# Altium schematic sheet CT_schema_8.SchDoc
size 277 x 170 mm
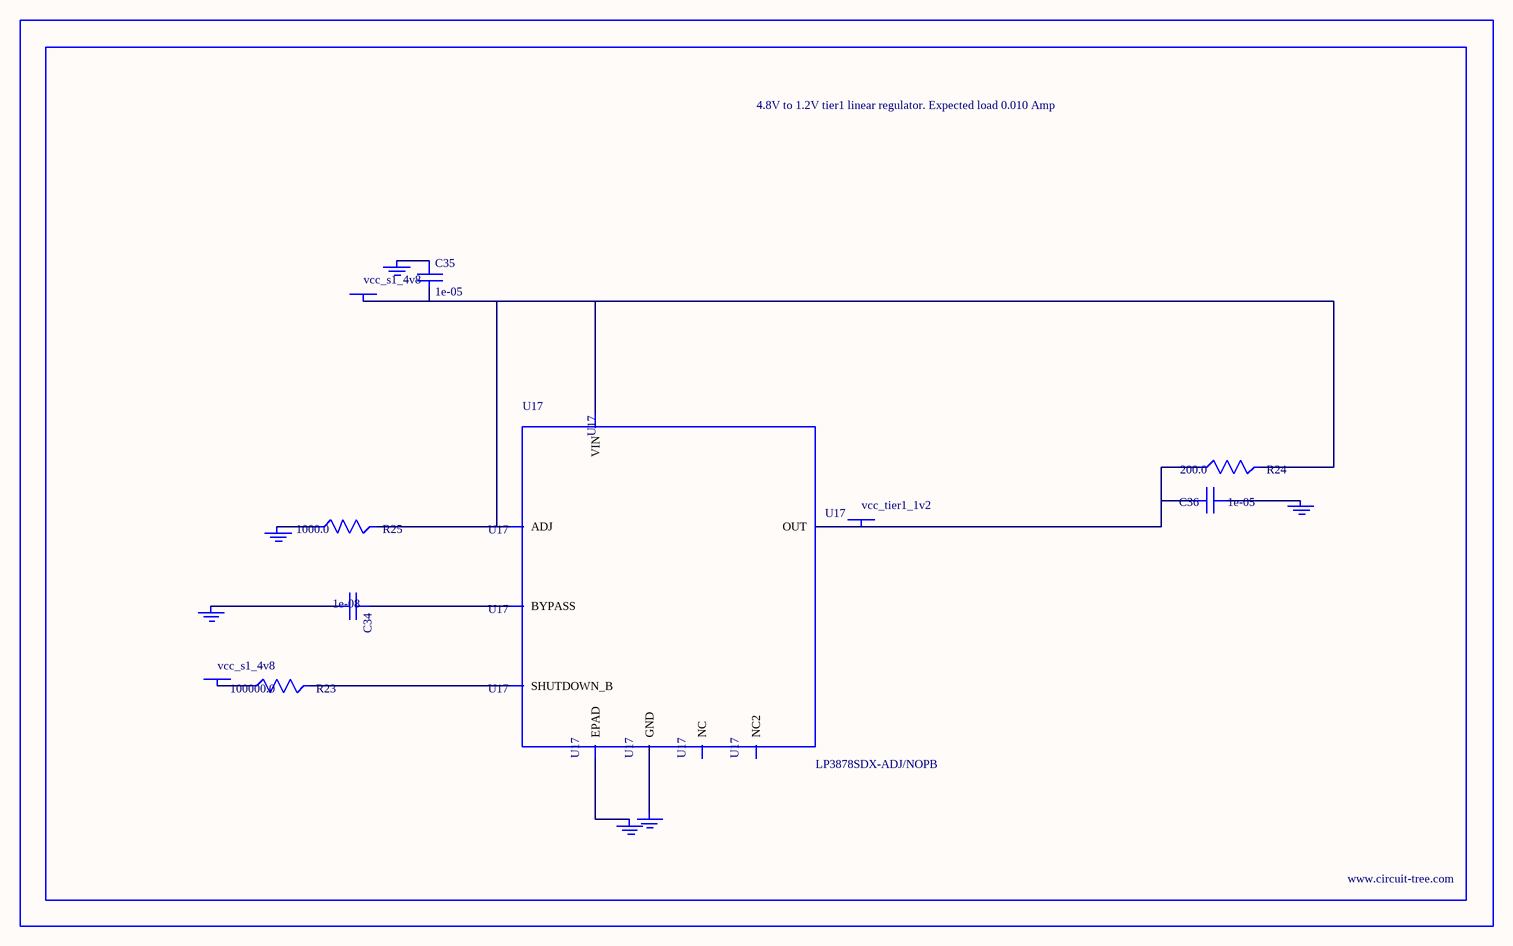
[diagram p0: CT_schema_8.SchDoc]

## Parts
BORDER7  (no value)
C34  1e-08  [C0402]
C35  1e-05  [C1206]
C36  1e-05  [C0805]
GND_INSTANCE_7_0  (no value)
GND_INSTANCE_7_1  (no value)
GND_INSTANCE_7_2  (no value)
GND_INSTANCE_7_3  (no value)
GND_INSTANCE_7_4  (no value)
GND_INSTANCE_7_5  (no value)
POWER_INSTANCE_7_0  vcc_s1_4v8
POWER_INSTANCE_7_1  vcc_s1_4v8
POWER_INSTANCE_7_2  vcc_tier1_1v2
R23  100000.0  [R0603]
R24  200.0  [R0603]
R25  1000.0  [R0603]
U17  LP3878SDX-ADJ/NOPB  [WSON-8]

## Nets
NetC34_1: C34.1 U17.1(BYPASS)
NetC34_2: C34.2 GND_INSTANCE_7_0.0(GND)
NetC35_1: C35.1 GND_INSTANCE_7_1.0(GND)
NetC35_2: C35.2 POWER_INSTANCE_7_0.0(PWR) R24.2 R25.2 U17.4(VIN) U17.6(ADJ)
NetC36_1: C36.1 GND_INSTANCE_7_2.0(GND)
NetC36_2: C36.2 POWER_INSTANCE_7_2.0(PWR) R24.1 U17.5(OUT)
NetGND_INSTANCE_7_3_0: GND_INSTANCE_7_3.0(GND) R25.1
NetGND_INSTANCE_7_4_0: GND_INSTANCE_7_4.0(GND) U17.PAD(EPAD)
NetGND_INSTANCE_7_5_0: GND_INSTANCE_7_5.0(GND) U17.3(GND)
NetPOWER_INSTANCE_7_1_0: POWER_INSTANCE_7_1.0(PWR) R23.1
NetR23_2: R23.2 U17.8(SHUTDOWN_B)

Not connected (* = marked no-connect by the designer): U17 2(NC) 7(NC2)

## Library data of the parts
BORDER7 = BORDER_PAGE7
C34 = C0402C103K3RAC
C35 = C1206C106K3RACTU
C36 = GRM219R60J106ME19D
GND_INSTANCE_7_0-GND_INSTANCE_7_5 = GND
POWER_INSTANCE_7_0-POWER_INSTANCE_7_2 = PWR
R23 = RC0603JR-07100KL
R24 = RC0603JR-07200RL
R25 = RC0603JR-071KL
